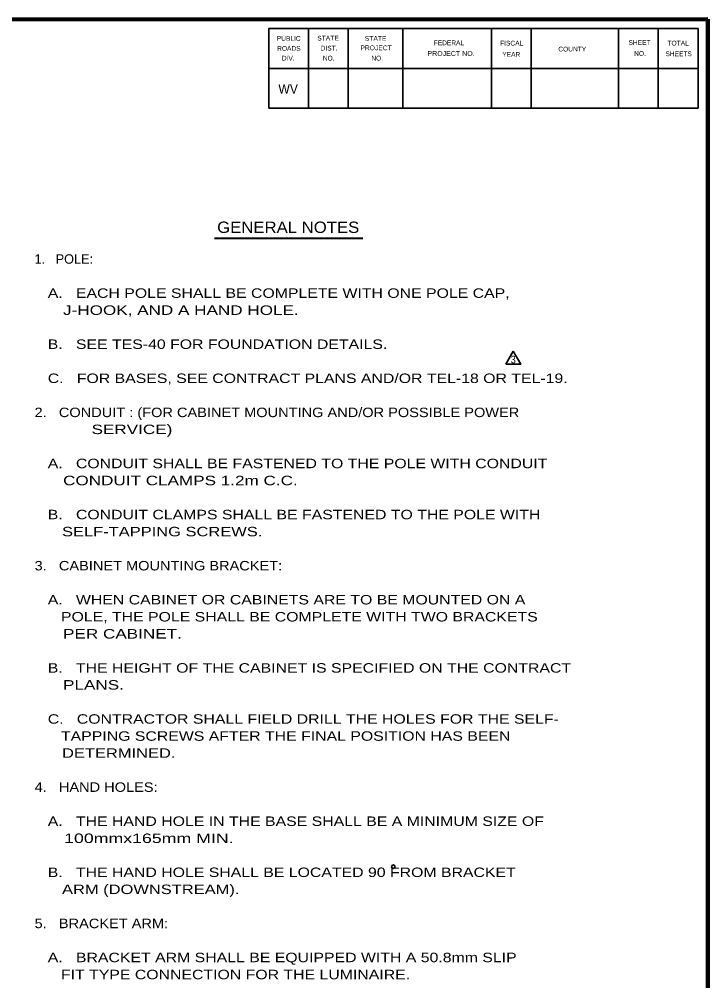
# Model space of a CAD drawing. Extents: x 6460 to 7173, y 270 to 723.
# Drawn here: x 6984.7 to 7167.9, y 461.8 to 717.8 of the extents above; entities that cross this region are included whole.
import ezdxf

# ---------------------------------------------------------------- set-up
doc = ezdxf.new("R2010")
doc.units = 0
doc.layers.add('1', color=7, linetype='Continuous', lineweight=35)
doc.layers.add('61', color=7, linetype='Continuous', lineweight=35)

msp = doc.modelspace()

# ---------------------------------------------------------------- linework, layer by layer
at = {"layer": '1', "lineweight": 158}
msp.add_line((7167.871, 279.382), (7167.871, 717.799), dxfattribs=at)
at = {"layer": '1', "lineweight": 13}
msp.add_line((7167.871, 279.382), (7167.871, 717.799), dxfattribs=at)
at = {"layer": '1', "lineweight": 40}
msp.add_line((7036.624, 659.512), (7076.064, 659.512), dxfattribs=at)
at = {"layer": '1'}
msp.add_line((7116.109, 629.377), (7114.109, 625.913), dxfattribs=at)
at = {"layer": '1', "lineweight": 158}
msp.add_lwpolyline([(7167.871, 717.799), (6508.121, 717.715), (6508.204, 279.382)], dxfattribs=at)
at = {"layer": '1'}
msp.add_lwpolyline([(7116.109, 629.377), (7118.109, 625.913), (7114.109, 625.913)], dxfattribs=at)
msp.add_circle((7084.216, 492.148), 0.481, dxfattribs=at)
at = {"layer": '61'}
for p, q in [((7061.621, 715.299), (7061.621, 694.132)), ((7072.204, 715.299), (7072.204, 694.132)), ((7086.704, 715.299), (7086.704, 694.132)), ((7110.287, 715.299), (7110.287, 694.132)), ((7120.871, 715.299), (7120.871, 694.132)), ((7144.121, 715.299), (7144.121, 694.132)), ((7154.704, 715.299), (7154.704, 694.132)), ((7165.287, 704.715), (7051.037, 704.715))]:
    msp.add_line(p, q, dxfattribs=at)
for points in [[(7165.287, 715.299), (7051.037, 715.299), (7051.037, 694.132)], [(7165.287, 715.299), (7165.287, 694.132), (7051.037, 694.132)]]:
    msp.add_lwpolyline(points, dxfattribs=at)

# ---------------------------------------------------------------- texts
at = {"layer": '1'}
for s, height, width, p in [('WV', 2.54, 0.95, (7053.621, 697.965)), ('GENERAL NOTES', 3.024, 1.1, (7037.324, 660.892)), ('   A.   EACH POLE SHALL BE COMPLETE WITH ONE POLE CAP,', 2.52, 1.25, (6988.744, 643.612)), ('      J-HOOK, AND A HAND HOLE.', 2.52, 1.35, (6988.744, 639.072)), ('   B.   SEE TES-40 FOR FOUNDATION DETAILS.', 2.52, 1.25, (6988.744, 630.012)), ('3', 2, 0.9, (7115.441, 626.181)), ('   C.   FOR BASES, SEE CONTRACT PLANS AND/OR TEL-18 OR TEL-19.', 2.52, 1.25, (6988.744, 620.932)), ('2.   CONDUIT : (FOR CABINET MOUNTING AND/OR POSSIBLE POWER', 2.52, 1.15, (6988.744, 611.852)), ('            SERVICE)', 2.52, 1.35, (6988.744, 607.332)), ('   A.   CONDUIT SHALL BE FASTENED TO THE POLE WITH CONDUIT', 2.52, 1.25, (6988.744, 598.252)), ('      CONDUIT CLAMPS 1.2m C.C.', 2.52, 1.35, (6988.744, 593.712)), ('   B.   CONDUIT CLAMPS SHALL BE FASTENED TO THE POLE WITH', 2.52, 1.25, (6988.744, 584.652)), ('      SELF-TAPPING SCREWS.', 2.52, 1.3, (6988.744, 580.112)), ('3.   CABINET MOUNTING BRACKET:', 2.52, 1.15, (6988.744, 571.032)), ('   A.   WHEN CABINET OR CABINETS ARE TO BE MOUNTED ON A', 2.52, 1.25, (6988.744, 561.972)), ('      POLE, THE POLE SHALL BE COMPLETE WITH TWO BRACKETS', 2.52, 1.25, (6988.744, 557.432)), ('      PER CABINET.', 2.52, 1.35, (6988.744, 552.892)), ('   B.   THE HEIGHT OF THE CABINET IS SPECIFIED ON THE CONTRACT', 2.52, 1.25, (6988.744, 543.812)), ('      PLANS.', 2.52, 1.35, (6988.744, 539.292)), ('   C.   CONTRACTOR SHALL FIELD DRILL THE HOLES FOR THE SELF-', 2.52, 1.25, (6988.744, 530.212)), ('      TAPPING SCREWS AFTER THE FINAL POSITION HAS BEEN', 2.52, 1.25, (6988.744, 525.672)), ('      DETERMINED.', 2.52, 1.3, (6988.744, 521.132)), ('4.   HAND HOLES:', 2.52, 1.15, (6988.744, 512.072)), ('   A.   THE HAND HOLE IN THE BASE SHALL BE A MINIMUM SIZE OF', 2.52, 1.25, (6988.744, 502.992)), ('      100mmx165mm MIN.', 2.52, 1.4, (6988.744, 498.452)), ('   B.   THE HAND HOLE SHALL BE LOCATED 90 FROM BRACKET', 2.52, 1.25, (6988.744, 489.392)), ('      ARM (DOWNSTREAM).', 2.52, 1.3, (6988.744, 484.852)), ('5.   BRACKET ARM:', 2.52, 1.15, (6988.744, 475.772)), ('   A.   BRACKET ARM SHALL BE EQUIPPED WITH A 50.8mm SLIP', 2.52, 1.25, (6988.744, 466.712)), ('      FIT TYPE CONNECTION FOR THE LUMINAIRE.', 2.52, 1.25, (6988.744, 462.172))]:
    msp.add_text(s, height=height, dxfattribs=dict(at, width=width)).set_placement(p)
msp.add_text('1.   POLE:', height=2.52, dxfattribs=at).set_placement((6988.744, 652.692))
at = {"layer": '61'}
for s, height, rotation, p in [('PUBLIC', 1.271, 0.033, (7053.204, 712.049)), ('FEDERAL', 1.27, 0.007, (7094.954, 710.882)), ('FISCAL', 1.271, 359.942, (7112.621, 710.799)), ('SHEET', 1.271, 0.059, (7146.787, 710.965)), ('ROADS', 1.27, 0.124, (7053.287, 709.382)), ('DIST.', 1.27, 0.056, (7064.871, 709.465)), ('COUNTY', 1.269, 0.069, (7128.121, 709.215)), ('SHEETS', 1.269, 359.959, (7156.621, 707.965)), ('DIV.', 1.27, 359.932, (7054.537, 706.799)), ('YEAR', 1.27, 0.105, (7113.204, 707.799))]:
    msp.add_text(s, height=height, rotation=rotation, dxfattribs=at).set_placement(p)
for s, height, rotation, width, p in [('STATE', 1.271, 0.059, 1.05, (7063.954, 712.132)), ('STATE', 1.271, 0.059, 1.05, (7076.621, 712.049)), ('TOTAL', 1.27, 359.926, 1.05, (7157.121, 710.799)), ('PROJECT', 1.27, 359.908, 1.05, (7075.454, 709.549)), ('PROJECT NO.', 1.27, 359.922, 1.1, (7093.287, 708.049)), ('NO.', 1.27, 359.852, 0.9, (7148.287, 708.049)), ('NO.', 1.27, 359.852, 0.9, (7065.454, 706.799)), ('NO.', 1.271, 0.225, 0.9, (7078.371, 706.799))]:
    msp.add_text(s, height=height, rotation=rotation, dxfattribs=dict(at, width=width)).set_placement(p)

doc.saveas('drawing.dxf')
